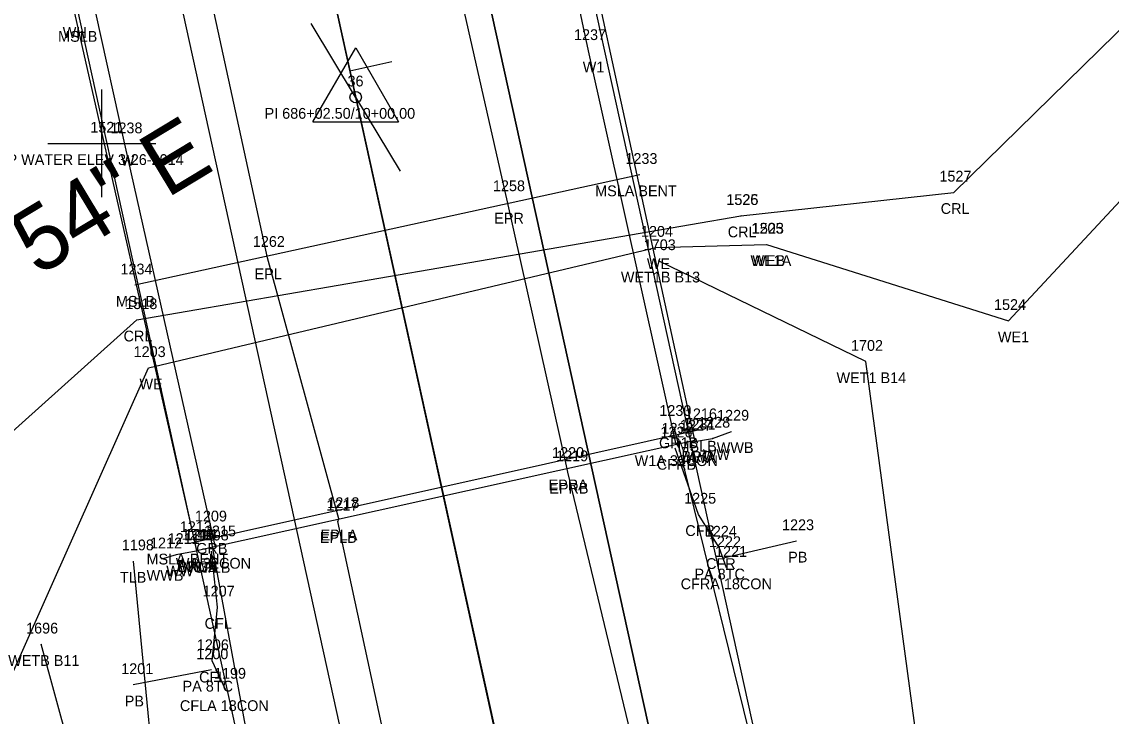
# Model space of a CAD drawing. Extents: x 2521558 to 2524785, y 882711 to 887632.
# Drawn here: x 2523758.7 to 2523859.8, y 885062.2 to 885126.7 of the extents above; entities that cross this region are included whole.
import ezdxf

# ---------------------------------------------------------------- set-up
doc = ezdxf.new("R2010")
doc.units = 0
for name, color, linetype in [('RD_EV_JurisArea', 7, 'Continuous'), ('RD_EX_BldgApp', 7, 'Continuous'), ('RD_EX_BldgApp_txCode', 7, 'Continuous'), ('RD_EX_Bridge', 7, 'Continuous'), ('RD_EX_Bridge_txCode', 7, 'Continuous'), ('RD_EX_Conc', 7, 'Continuous'), ('RD_EX_Conc_txCode', 7, 'Continuous'), ('RD_EX_DR_Pipe', 7, 'Continuous'), ('RD_EX_DR_Pipe_txCode', 7, 'Continuous'), ('RD_EX_GuardRail', 7, 'Continuous'), ('RD_EX_GuardRail_txCode', 7, 'Continuous'), ('RD_EX_H2O', 7, 'Continuous'), ('RD_EX_H2O_txCode', 7, 'Continuous'), ('RD_EX_H2O_WetLd_txCode', 7, 'Continuous'), ('RD_EX_Misc', 7, 'Continuous'), ('RD_EX_Misc_txCode', 7, 'Continuous'), ('RD_EX_Road', 7, 'Continuous'), ('RD_EX_Road_txCode', 7, 'Continuous'), ('RD_EX_VEG', 7, 'Continuous'), ('RD_EX_VEG_txCode', 7, 'Continuous'), ('RD_HC_Cl', 7, 'Continuous'), ('RD_HC_Data', 7, 'Continuous'), ('RD_HC_Data_Tic', 7, 'Continuous'), ('RD_HC_txCode', 7, 'Continuous'), ('RD_PD_Bridge', 7, 'Continuous'), ('RD_PD_Final_TrvlWay', 7, 'Continuous'), ('RD_PD_SuperShp1', 7, 'Continuous'), ('RD_SMD_Locator', 7, 'Continuous')]:
    doc.layers.add(name, color=color, linetype=linetype)

msp = doc.modelspace()

# ---------------------------------------------------------------- linework, layer by layer
at = {"layer": 'RD_EV_JurisArea'}
for points in [[(2523944.86, 884550.08), (2523910.41, 884709.58), (2523888.01, 884815.03), (2523863.93, 884918.37), (2523848.43, 885010.84), (2523837.07, 885095.13), (2523817.82, 885104.47)], [(2523827.75, 884469.64), (2523867.43, 884517.67), (2523885.95, 884534.84), (2523882.77, 884582.72), (2523847.74, 884736.42), (2523822.93, 884833.79), (2523804.26, 884914.89), (2523780.91, 884992.76), (2523770.73, 885031.48), (2523760.5, 885068.9)]]:
    msp.add_lwpolyline(points, dxfattribs=at)
at = {"layer": 'RD_EX_BldgApp'}
for points in [[(2523819.44, 885087.44), (2523811.32, 885123.96), (2523803.31, 885161.5)], [(2523776.68, 885077.92), (2523768.27, 885115.31), (2523760.2, 885151.9)]]:
    msp.add_lwpolyline(points, dxfattribs=at)
at = {"layer": 'RD_EX_Bridge'}
for points in [[(2523774.91, 885077.6), (2523821.2, 885087.83), (2523805.06, 885161.89), (2523758.15, 885151.44), (2523774.91, 885077.6)], [(2523821.15, 885087.73), (2523822.84, 885088), (2523824.6, 885088.65)], [(2523774.9, 885077.54), (2523773.02, 885077.21), (2523771.67, 885076.8)]]:
    msp.add_lwpolyline(points, dxfattribs=at)
at = {"layer": 'RD_EX_Conc'}
for points in [[(2523824.12, 885076.01), (2523823.45, 885077.89), (2523821.53, 885080.95), (2523819.36, 885087.1)], [(2523777.61, 885064.71), (2523776.36, 885067.36), (2523776.88, 885072.34), (2523776.32, 885077.54)]]:
    msp.add_lwpolyline(points, dxfattribs=at)
at = {"layer": 'RD_EX_DR_Pipe'}
for p, q in [((2523823.84, 885076.92), (2523830.63, 885078.49)), ((2523776.32, 885066.52), (2523769.04, 885065.14))]:
    msp.add_line(p, q, dxfattribs=at)
at = {"layer": 'RD_EX_GuardRail'}
for points in [[(2523841.11, 885013.81), (2523827.6, 885055.26), (2523819.28, 885089.09)], [(2523787.38, 885001.58), (2523782.91, 885042.69), (2523776.15, 885079.3)]]:
    msp.add_lwpolyline(points, dxfattribs=at)
at = {"layer": 'RD_EX_H2O'}
for points in [[(2523582.82, 884766.34), (2523598.11, 884856.98), (2523627.59, 884901.75), (2523623.76, 884928.28), (2523586.58, 884955.43), (2523600.94, 884974.12), (2523633.05, 884997.68), (2523679.17, 885037.05), (2523744.72, 885076.89), (2523769.38, 885099), (2523825.47, 885108.66), (2523825.47, 885108.66), (2523845.24, 885110.83), (2523890.25, 885154.93)], [(2523827.83, 885106), (2523850.3, 885098.92), (2523867.33, 885117.19), (2523890.44, 885097.24), (2523927.79, 885098.78), (2523966.35, 885109.5), (2523978.17, 885083.37)], [(2523792.73, 884941.12), (2523763.67, 885051.56), (2523756.26, 885062.72), (2523770.47, 885094.55), (2523817.57, 885105.71), (2523827.83, 885106)]]:
    msp.add_lwpolyline(points, dxfattribs=at)
at = {"layer": 'RD_EX_Misc'}
for p, q in [((2523766.13, 885110.37), (2523766.13, 885120.37)), ((2523761.13, 885115.37), (2523771.13, 885115.37)), ((2523816.08, 885112.47), (2523769.2, 885102.22)), ((2523774.43, 885078.31), (2523821.35, 885088.78))]:
    msp.add_line(p, q, dxfattribs=at)
at = {"layer": 'RD_EX_Road'}
for p, q in [((2523803.79, 885109.94), (2523798.3, 885134.14)), ((2523781.52, 885104.77), (2523776.18, 885129.21)), ((2523809.32, 885085.19), (2523803.79, 885109.94)), ((2523788.14, 885080.54), (2523781.52, 885104.77)), ((2523809.38, 885084.88), (2523809.32, 885085.19)), ((2523817.58, 885050.92), (2523809.38, 885084.88)), ((2523788.05, 885080.31), (2523788.14, 885080.54)), ((2523795.47, 885045.91), (2523788.05, 885080.31))]:
    msp.add_line(p, q, dxfattribs=at)
at = {"layer": 'RD_EX_VEG'}
msp.add_lwpolyline([(2523800.23, 884418.22), (2523892.24, 884498.97), (2523844.57, 884752.81), (2523771.94, 885046.88), (2523769.06, 885076.62)], dxfattribs=at)
at = {"layer": 'RD_HC_Cl'}
msp.add_line((2523641.17, 885794.2), (2524197.76, 883266.56), dxfattribs=at)
at = {"layer": 'RD_HC_Data'}
for p, q in [((2523785.73, 885117.37), (2523789.7, 885124.25)), ((2523789.7, 885124.25), (2523793.67, 885117.37)), ((2523785.73, 885117.37), (2523793.67, 885117.37))]:
    msp.add_line(p, q, dxfattribs=at)
msp.add_circle((2523789.7, 885119.66), 0.529, dxfattribs=at)
at = {"layer": 'RD_HC_Data_Tic'}
for p, q in [((2523789.69, 885119.66), (2523785.56, 885126.5)), ((2523789.16, 885122.1), (2523793.07, 885122.96)), ((2523789.69, 885119.66), (2523793.83, 885112.81))]:
    msp.add_line(p, q, dxfattribs=at)
at = {"layer": 'RD_PD_Bridge'}
for points in [[(2523830.93, 885041.7), (2523794.37, 885207.73)], [(2523748.47, 885197.62), (2523785.03, 885031.6)]]:
    msp.add_lwpolyline(points, dxfattribs=at)
at = {"layer": 'RD_PD_Final_TrvlWay'}
for p, q in [((2523724.34, 885481.57), (2524039.39, 884050.85)), ((2523697, 885475.55), (2524012.05, 884044.83))]:
    msp.add_line(p, q, dxfattribs=at)
at = {"layer": 'RD_PD_SuperShp1'}
for p, q in [((2524039.39, 884050.85), (2523724.34, 885481.57)), ((2524025.72, 884047.84), (2523710.67, 885478.56)), ((2523710.67, 885478.56), (2524025.72, 884047.84)), ((2523697, 885475.55), (2524012.05, 884044.83))]:
    msp.add_line(p, q, dxfattribs=at)
at = {"layer": 'RD_SMD_Locator'}
for centre in [(2523811.32, 885123.96), (2523789.7, 885119.66), (2523768.27, 885115.31), (2523816.08, 885112.47), (2523845.24, 885110.83), (2523803.79, 885109.94), (2523825.47, 885108.66), (2523825.47, 885108.66), (2523817.57, 885105.71), (2523827.83, 885106), (2523827.83, 885106), (2523781.52, 885104.77), (2523817.82, 885104.47), (2523769.2, 885102.22), (2523769.38, 885099), (2523850.3, 885098.92), (2523770.47, 885094.55), (2523837.07, 885095.13), (2523819.28, 885089.09), (2523821.35, 885088.78), (2523824.6, 885088.65), (2523819.44, 885087.44), (2523821.15, 885087.73), (2523821.2, 885087.83), (2523822.84, 885088), (2523819.36, 885087.1), (2523809.32, 885085.19), (2523809.38, 885084.88), (2523788.05, 885080.31), (2523788.14, 885080.54), (2523821.53, 885080.95), (2523776.15, 885079.3), (2523774.43, 885078.31), (2523830.63, 885078.49), (2523773.02, 885077.21), (2523774.9, 885077.54), (2523774.91, 885077.6), (2523774.91, 885077.6), (2523776.32, 885077.54), (2523776.68, 885077.92), (2523823.45, 885077.89), (2523769.06, 885076.62), (2523771.67, 885076.8), (2523823.84, 885076.92), (2523824.12, 885076.01), (2523776.88, 885072.34), (2523760.5, 885068.9), (2523776.36, 885067.36), (2523776.32, 885066.52), (2523769.04, 885065.14), (2523777.61, 885064.71)]:
    msp.add_circle(centre, 0.001, dxfattribs=at)

# ---------------------------------------------------------------- texts
at = {"layer": 'RD_EX_BldgApp_txCode'}
for s, p in [('WH', (2523762.5, 885125.16)), ('1237', (2523809.97, 885124.96)), ('W1', (2523810.78, 885121.96)), ('1238', (2523766.93, 885116.31)), ('W', (2523767.9, 885113.31)), ('1232', (2523818.09, 885088.44)), ('W1A 32CON', (2523815.6, 885085.44)), ('1215', (2523775.61, 885078.92)), ('WA 32CON', (2523773, 885075.92))]:
    msp.add_text(s, height=1, dxfattribs=at).set_placement(p)
at = {"layer": 'RD_EX_Bridge_txCode'}
for s, p in [('1229', (2523823.25, 885089.65)), ('1227', (2523819.8, 885088.73)), ('1231', (2523820.13, 885088.83)), ('1228', (2523821.49, 885089)), ('WWB', (2523823.22, 885086.65)), ('WWA', (2523819.75, 885085.73)), ('BRC', (2523819.95, 885085.83)), ('WW', (2523821.93, 885086)), ('1211', (2523772.24, 885078.21)), ('1246', (2523773.54, 885078.6)), ('1210', (2523773.79, 885078.54)), ('1214', (2523773.84, 885078.6)), ('1212', (2523770.6, 885077.8)), ('WW', (2523772.11, 885075.21)), ('BRCA', (2523773.17, 885075.6)), ('BRCB', (2523773.18, 885075.6)), ('WWA', (2523773.5, 885075.54)), ('WWB', (2523770.29, 885074.8))]:
    msp.add_text(s, height=1, dxfattribs=at).set_placement(p)
at = {"layer": 'RD_EX_Conc_txCode'}
for s, p in [('1226', (2523817.99, 885088.1)), ('CFRB', (2523817.66, 885085.1)), ('1225', (2523820.19, 885081.95)), ('1208', (2523774.94, 885078.54)), ('CFR', (2523820.3, 885078.95)), ('1224', (2523822.11, 885078.89)), ('1221', (2523823.06, 885077.01)), ('CFLB', (2523774.65, 885075.54)), ('CFR', (2523822.23, 885075.89)), ('1207', (2523775.49, 885073.34)), ('CFRA 18CON', (2523819.87, 885074.01)), ('CFL', (2523775.67, 885070.34)), ('1206', (2523774.95, 885068.36)), ('CFL', (2523775.16, 885065.36)), ('1199', (2523776.54, 885065.71)), ('CFLA 18CON', (2523773.38, 885062.71))]:
    msp.add_text(s, height=1, dxfattribs=at).set_placement(p)
at = {"layer": 'RD_EX_DR_Pipe_txCode'}
for s, p in [('1223', (2523829.28, 885079.49)), ('1222', (2523822.49, 885077.92)), ('PB', (2523829.85, 885076.49)), ('PA 8TC', (2523821.15, 885074.92)), ('1200', (2523774.9, 885067.52)), ('1201', (2523767.93, 885066.14)), ('PA 8TC', (2523773.63, 885064.52)), ('PB', (2523768.26, 885063.14))]:
    msp.add_text(s, height=1, dxfattribs=at).set_placement(p)
at = {"layer": 'RD_EX_GuardRail_txCode'}
for s, p in [('1230', (2523817.89, 885090.09)), ('GR1B', (2523817.86, 885087.09)), ('1209', (2523774.77, 885080.3)), ('GRB', (2523774.9, 885077.3))]:
    msp.add_text(s, height=1, dxfattribs=at).set_placement(p)
at = {"layer": 'RD_EX_H2O_txCode'}
for s, p in [('1527', (2523843.89, 885111.83)), ('1526', (2523824.1, 885109.66)), ('1525', (2523824.12, 885109.66)), ('CRL', (2523844.01, 885108.83)), ('1204', (2523816.18, 885106.71)), ('CRL', (2523824.24, 885106.66)), ('CRL', (2523824.24, 885106.66)), ('1205', (2523826.44, 885107)), ('1523', (2523826.48, 885107)), ('WE', (2523816.73, 885103.71)), ('WE1A', (2523826.35, 885104)), ('WEB', (2523826.53, 885104)), ('1518', (2523768.31, 885100)), ('1524', (2523848.96, 885099.92)), ('CRL', (2523768.15, 885097)), ('WE1', (2523849.32, 885096.92)), ('1203', (2523769.08, 885095.55)), ('WE', (2523769.63, 885092.55))]:
    msp.add_text(s, height=1, dxfattribs=at).set_placement(p)
at = {"layer": 'RD_EX_H2O_WetLd_txCode'}
for s, p in [('1703', (2523816.44, 885105.47)), ('WET1B B13', (2523814.32, 885102.47)), ('1702', (2523835.68, 885096.13)), ('WET1 B14', (2523834.34, 885093.13)), ('1696', (2523759.1, 885069.9)), ('WETB B11', (2523757.44, 885066.9))]:
    msp.add_text(s, height=1, dxfattribs=at).set_placement(p)
at = {"layer": 'RD_EX_Misc_txCode'}
for s, p in [('MSLB', (2523762.07, 885124.8)), ('1521', (2523765.06, 885116.37)), ('MSP WATER ELEV 3-26-2014', (2523755.37, 885113.37)), ('1233', (2523814.74, 885113.47)), ('MSLA BENT', (2523811.93, 885110.47)), ('1234', (2523767.86, 885103.22)), ('MSLB', (2523767.44, 885100.22)), ('1216', (2523820.26, 885089.78)), ('MSLB', (2523819.58, 885086.78)), ('1213', (2523773.37, 885079.31)), ('MSLA BENT', (2523770.28, 885076.31))]:
    msp.add_text(s, height=1, dxfattribs=at).set_placement(p)
at = {"layer": 'RD_EX_Road_txCode'}
for s, p in [('1258', (2523802.44, 885110.94)), ('EPR', (2523802.56, 885107.94)), ('1262', (2523780.15, 885105.77)), ('EPL', (2523780.31, 885102.77)), ('1220', (2523807.93, 885086.19)), ('1219', (2523808.31, 885085.88)), ('EPRA', (2523807.6, 885083.19)), ('EPRB', (2523807.67, 885082.88)), ('1217', (2523786.98, 885081.31)), ('1218', (2523787.07, 885081.54)), ('EPLB', (2523786.37, 885078.31)), ('EPLA', (2523786.44, 885078.54))]:
    msp.add_text(s, height=1, dxfattribs=at).set_placement(p)
at = {"layer": 'RD_EX_VEG_txCode'}
for s, p in [('1198', (2523767.99, 885077.62)), ('TLB', (2523767.81, 885074.62))]:
    msp.add_text(s, height=1, dxfattribs=at).set_placement(p)
at = {"layer": 'RD_HC_Data'}
msp.add_text('N 58%%d 52\' 54" E', height=6, rotation=31.1184, dxfattribs=at).set_placement((2523730.14, 885084.87))
at = {"layer": 'RD_HC_txCode'}
for s, p in [('36', (2523788.94, 885120.66)), ('PI 686+02.50/10+00.00', (2523781.24, 885117.66))]:
    msp.add_text(s, height=1, dxfattribs=at).set_placement(p)

doc.saveas('drawing.dxf')
